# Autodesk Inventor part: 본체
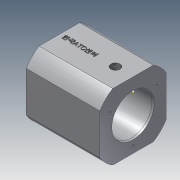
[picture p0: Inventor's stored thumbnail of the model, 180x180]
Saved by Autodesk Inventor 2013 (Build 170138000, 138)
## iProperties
Created: 2020-02
Part Number: 본체
Material: 알루미늄 6061
Document SubType Name: Modeling
Designer: CADCOM
Density: 2.71 g/cm^3
Mass: 540.135 g
Surface Area: 341.963 cm^2
Volume: 199.312 cm^3
Author: CADCOM
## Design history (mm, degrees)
sketch "스케치1"
  geometry: L1 (-32, -32)-(32, -32); L2 (32, -32)-(32, 32); L3 (32, 32)-(-32, 32); L4 (-32, 32)-(-32, -32); L5 (-32, -32)-(32, 32); L6 (32, -32)-(-32, 32); 1 further point
  constraints: 12 end point, 2 midpoint, 2 parallel, 1 horizontal, 1 perpendicular
  dimensions: "d0" = 64 distance of L3.end L2.end; "d1" = 64 distance of L2.end L1.end
extrude "돌출1" new body sketch "스케치1" distance "d3" = 71; taper "d4" = 0 deg
sketch "스케치2" dims "d5" = 75
  geometry: L1 (-32, -32)-(32, -32) reference; L2 (32, -32)-(32, 32) reference; L3 (32, 32)-(-32, 32) reference; L4 (-32, 19.551)-(-32, -19.551); L5 (-32, 19.551)-(-32, 32); L6 (-32, 32)-(-19.551, 32); L7 (-32, -19.551)-(-32, -32); L8 (-32, -32)-(-19.551, -32); L9 (19.551, -32)-(32, -32); L10 (32, -32)-(32, -19.551); L11 (32, 19.551)-(32, 32); L12 (32, 32)-(19.551, 32); 2 further points
  constraints: 18 end point, 6 point on line, 3 collinear, 1 coincident, 1 perpendicular, 10 other
extrude "돌출2" cut sketch "스케치2" stored distance "d6" = 71; taper "d7" = 0 deg
sketch "스케치3"
  geometry: C1 r 20 at (0, 0); A1 r 37.5 centre (0, 0) between (19.551, -32) and (32, -19.551) reference
  constraints: 1 centre point, 1 coincident
  dimensions: "d8" = 40 diameter of C1
extrude "돌출3" cut sketch "스케치3" distance "d9" = 62; taper "d10" = 0 deg
sketch "스케치4"
  geometry: C1 r 14 at (0, 0); A1 r 37.5 centre (0, 0) between (32, 19.551) and (19.551, 32) reference
  constraints: 1 centre point, 1 coincident
  dimensions: "d11" = 28 diameter of C1
extrude "돌출4" join sketch "스케치4" distance "d12" = 12; taper "d13" = 0 deg
sketch "스케치5"
  geometry: C1 r 14 at (0, 0) reference; 1 further point
  constraints: 1 coincident
hole "구멍1" sketch "스케치5" at (0, 0) diameter "d14" = 8.917; stored, may be unused: countersink angle "d18" = 90 deg, drill point angle "d20" = 118 deg; dims "d15" = 14, "d16" = 4, "d17" = 2, "d19" = 17
node "작업 평면1"
sketch "스케치7"
  geometry: C1 r 2 at (0, 0); 1 further point
  constraints: 1 centre point, 1 coincident
  dimensions: "d23" = 4 diameter of C1
extrude "돌출5" cut sketch "스케치7" distance "d24" = 12; taper "d25" = 0 deg
sketch "스케치8"
  geometry: L1 (19.551, 32)-(-19.551, 32) reference; L2 (0, 0)-(0, 26); A1 r 37.5 centre (0, 0) between (32, 19.551) and (19.551, 32) reference; 1 further point
  constraints: 2 end point, 1 coincident, 1 perpendicular
  dimensions: "d26" = 26 distance of L2.start L2.end
hole "구멍2" sketch "스케치8" at (0, 26) diameter "d27" = 3.242; stored, may be unused: countersink angle "d31" = 90 deg, drill point angle "d33" = 118 deg; dims "d28" = 10, "d29" = 4, "d30" = 2, "d32" = 12
sketch "스케치9"
  geometry: L1 (39.102, 0)-(0, 0) reference; L2 (19.551, 0)-(19.551, 17); 1 further point
  constraints: 2 end point, 1 coincident, 1 perpendicular
  dimensions: "d37" = 17 distance of L2.start L2.end
hole "구멍3" sketch "스케치9" at (19.551, 17) diameter "d38" = 8.917; stored, may be unused: countersink angle "d42" = 90 deg, drill point angle "d44" = 118 deg; dims "d39" = 6, "d40" = 4, "d41" = 2, "d43" = 9
sketch "스케치13"
  geometry: L1 (19.551, 32)-(-19.551, 32) reference; L2 (-19.551, -32)-(19.551, -32) reference; L3 (32, -19.551)-(32, 19.551) reference; L4 (0, 0)-(0, 32); L5 (0, 0)-(-32.476, 18.75); L6 (0, 0)-(32, 18.475); L7 (0, 0)-(0, -32); A1 r 37.5 centre (0, 0) between (-19.551, 32) and (-32, 19.551) reference; A2 r 37.5 centre (0, 0) between (19.551, -32) and (32, -19.551) reference; A3 r 26 centre (0, 0) between (-22.517, 13) and (22.517, 13); 1 further point
  constraints: 8 end point, 4 point on circle, 4 point on line, 2 midpoint, 1 centre point, 1 coincident
  dimensions: "d56" = 52 diameter of A3; "d57" = 60 deg angle of L4 L5; "d59" = 60 deg angle of L6 L4
hole "구멍4" sketch "스케치13" at (-22.517, 13), (22.517, 13), (0, -26) diameter "d61" = 2.459; stored, may be unused: countersink angle "d65" = 90 deg, drill point angle "d67" = 118 deg; dims "d62" = 10, "d63" = 4, "d64" = 2, "d66" = 12
chamfer "모따기1" distance "d68" = 1.8; stored, may be unused: second distance "d69" = 2, angle "d70" = 15 deg
chamfer "모따기2" distance "d71" = 1; stored, may be unused: second distance "d72" = 2, angle "d73" = 15 deg
chamfer "모따기3" distance "d74" = 1; stored, may be unused: second distance "d75" = 2, angle "d76" = 15 deg
sketch "스케치14"
  geometry: L1 (0, 71)-(39.102, 71) reference; L2 (19.551, 17)-(19.551, 71); C1 r 4.458 at (19.551, 17) reference; 3 further points
  constraints: 2 end point, 1 midpoint, 1 point on line, 1 other
  dimensions: "d77" = 20 distance from line of point (19.551, 51) L1
feature "엠보싱1" sketch "스케치14" dims "d0" = 64, "d1" = 64, "d79" = 0.5, "d80" = 0
node "작업 평면5"
sketch "스케치15"
  geometry: L1 (0, 0)-(0, -17); C1 r 2 at (0, -17)
  constraints: 2 end point, 1 centre point, 1 coincident, 1 vertical
  dimensions: "d82" = 17 distance of L1.start L1.end; "d83" = 4 diameter of C1
extrude "돌출7" cut sketch "스케치15" stored distance "d84" = 35; taper "d85" = 0 deg
sketch "스케치16"
  geometry: 1 further point
node "솔리드1"
pattern_circular "원형 패턴1" dims angle "d35" = 360 deg
other parameters: "d22" = -62
